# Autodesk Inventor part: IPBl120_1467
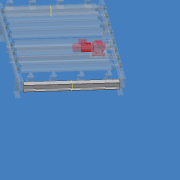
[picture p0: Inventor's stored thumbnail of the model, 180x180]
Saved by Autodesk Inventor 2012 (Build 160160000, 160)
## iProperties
Company: CAD-Verlag
Shininess: 64.0
Length Units: 11269
Angle Units: 11279
Time Units: 11290
Mass Units: 11283
Length Display Precision: 3
Angle Display Precision: 2
Compacted: True
Part Number: IPBl120_1467
Document SubType Name: Modeling
Created: 2004-09
Material: Standard
Designer: Greiling
Manufacturer: Standard
Standards Organization: Custom
Density: 1 g/cm^3
Density: 0.0
Volumn: 0.0
Area: 0.0
PropertySet Name: Model Information
Control State: 0
Master: False
Checked Out: False
Author: Jürgen Kronas
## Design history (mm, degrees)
sketch "Skizze1"
  geometry: L1 (0, 148.2)-(0, -11.4) reference; L2 (-12, 0)-(156, 0) reference; L3 (-12, 0)-(156, 0) reference; L4 (0, -11.4)-(0, 148.2) reference; L5 (120, 114)-(0, 114); L6 (120, 0)-(0, 0); L7 (74.5, 8)-(120, 8); L8 (120, 106)-(74.5, 106); L9 (120, 114)-(120, 106); L10 (120, 8)-(120, 0); L11 (57.5, 20)-(57.5, 94); L12 (62.5, 94)-(62.5, 20); L13 (0, 106)-(0, 114); L14 (45.5, 106)-(0, 106); L15 (0, 8)-(45.5, 8); L16 (0, 0)-(0, 8); A1 r 12 centre (74.5, 94) between (74.5, 106) and (62.5, 94); A2 r 12 centre (45.5, 94) between (57.5, 94) and (45.5, 106); A3 r 12 centre (74.5, 20) between (62.5, 20) and (74.5, 8); A4 r 12 centre (45.5, 20) between (45.5, 8) and (57.5, 20); 1 further point
  constraints: 24 end point, 8 point on circle, 4 centre point, 3 point on line
extrude "Extrusion1" new body sketch "Skizze1" distance "d0" = 1467; taper "d1" = 0 deg
workplane "Arbeitsebene4"
node "Volumenkörper1"
node "Volumenkörpern"
node "Oberflächenkörpern"
other parameters: "d3" = -733.5 (= -0.5 x d0)
